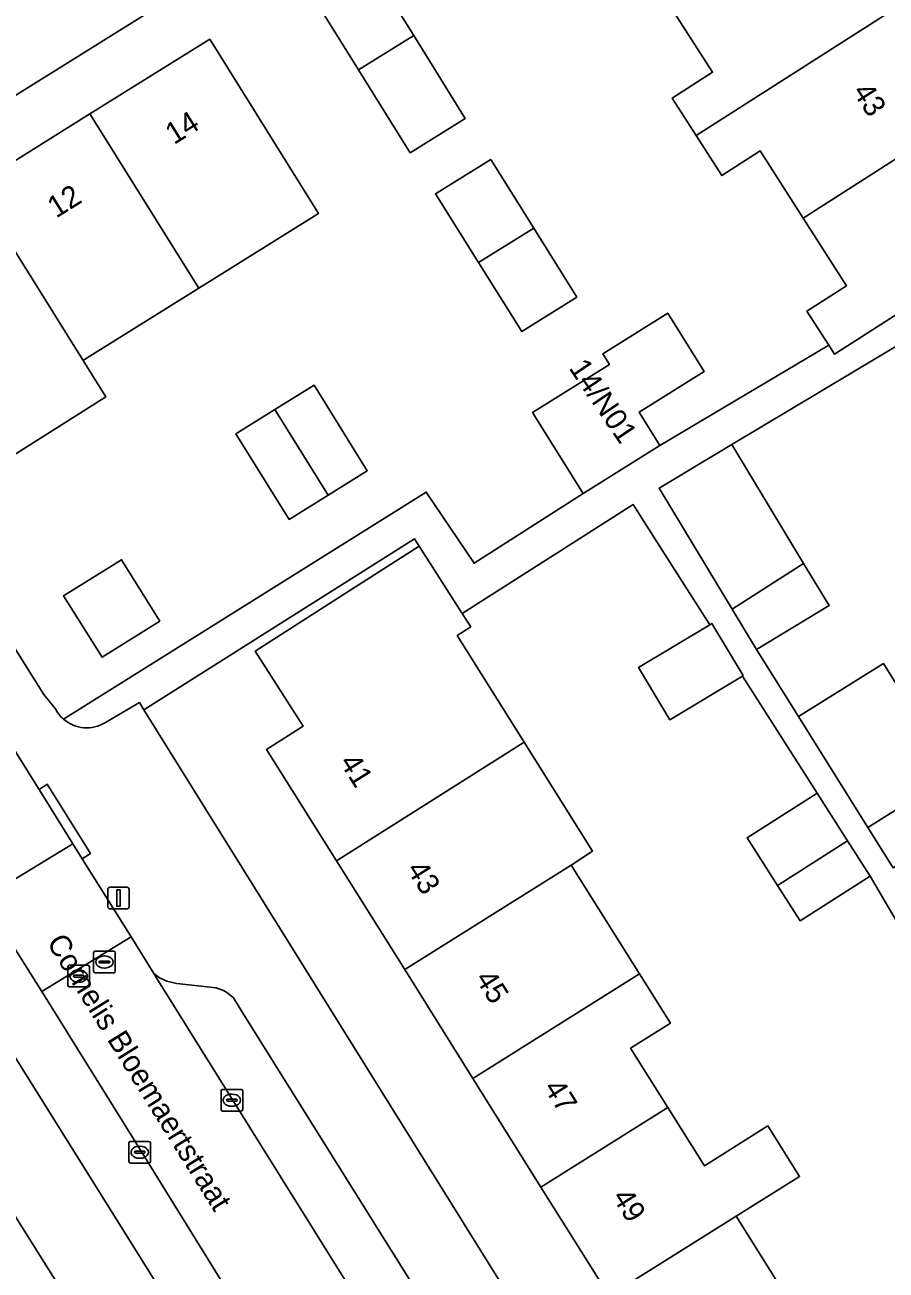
# Model space of a CAD drawing. Extents: x 159664 to 160323, y 385312 to 386115.
# Drawn here: x 160068.3 to 160108.1, y 385782.7 to 385840.2 of the extents above; entities that cross this region are included whole.
import ezdxf

# ---------------------------------------------------------------- set-up
doc = ezdxf.new("R2010")
doc.units = 0
for name, color, linetype in [('IMGEO_Erf', 7, 'Continuous'), ('IMGEO_Kolk', 7, 'Continuous'), ('IMGEO_Lichtmast', 7, 'Continuous'), ('IMGEO_Openbare_ruimte_label', 7, 'Continuous'), ('IMGEO_Pand', 7, 'Continuous'), ('IMGEO_Pand_nummerreeks', 7, 'Continuous'), ('IMGEO_Parkeervlak_open', 7, 'Continuous'), ('IMGEO_Rijbaan_lokaal_open', 7, 'Continuous'), ('IMGEO_Rioolput', 7, 'Continuous'), ('IMGEO_Voetpad_open', 7, 'Continuous')]:
    doc.layers.add(name, color=color, linetype=linetype)

msp = doc.modelspace()

# ---------------------------------------------------------------- linework, layer by layer
at = {"layer": 'IMGEO_Erf'}
for points in [[(160099.993, 385857.035), (160056.287, 385829.749), (160069.138, 385809.263), (160069.666, 385808.627)], [(160086.806, 385818.618), (160089.016, 385815.333), (160094.051, 385818.558), (160091.722, 385822.304), (160095.272, 385824.511), (160094.96, 385825.013), (160097.966, 385826.883), (160099.644, 385824.185), (160096.637, 385822.315), (160097.601, 385820.765), (160105.402, 385825.407), (160104.395, 385826.978), (160106.228, 385828.152), (160104.224, 385831.28), (160102.237, 385834.382), (160100.465, 385833.247), (160099.285, 385835.089), (160098.172, 385836.826), (160100.037, 385838.02), (160097.783, 385841.539)], [(160109.115, 385825.717), (160100.925, 385820.823), (160104.238, 385815.326), (160105.416, 385813.372), (160102.062, 385811.351), (160104.012, 385808.255), (160107.927, 385810.699), (160111.128, 385805.573)], [(160070.045, 385808.133), (160086.806, 385818.618)], [(160111.176, 385794.277), (160107.313, 385800.874), (160104.076, 385798.81), (160103.033, 385800.445), (160101.627, 385802.649), (160104.864, 385804.713), (160101.416, 385810.12), (160098.061, 385808.099), (160096.609, 385810.51), (160099.902, 385812.494), (160097.599, 385816.106), (160096.366, 385818.04), (160088.474, 385813.007), (160088.865, 385812.396), (160088.236, 385811.993), (160091.332, 385807.058), (160094.486, 385802.031), (160093.507, 385801.382), (160096.658, 385796.361), (160098.084, 385794.087), (160096.249, 385792.925), (160097.968, 385790.185), (160099.656, 385787.495), (160102.592, 385789.336), (160104.054, 385787.003), (160101.119, 385785.163), (160104.27, 385780.142)], [(160095.257, 385781.488), (160092.108, 385786.51), (160088.959, 385791.532), (160085.81, 385796.554), (160082.66, 385801.577), (160079.432, 385806.725), (160081.117, 385807.804), (160078.901, 385811.265), (160083.112, 385813.961), (160086.481, 385816.118), (160086.259, 385816.465), (160073.759, 385808.564), (160107.875, 385753.788)], [(160094.38, 385750), (160062.581, 385800.858), (160046.077, 385790.539), (160045.381, 385790.102), (160047.281, 385787.076), (160041.478, 385783.432), (160042.208, 385782.014), (160044.187, 385783.22), (160046.139, 385780.014)], [(160058.795, 385780.788), (160055.579, 385785.924), (160056.192, 385786.308), (160052.934, 385791.512), (160054.578, 385792.541), (160056.533, 385793.765), (160060.771, 385796.418), (160064.029, 385791.215), (160067.245, 385786.079), (160070.46, 385780.943)]]:
    msp.add_lwpolyline(points, dxfattribs=at)
for points in [[(160081.3, 385841.944), (160083.846, 385843.53), (160086.227, 385839.709), (160088.607, 385835.888), (160086.061, 385834.302), (160083.68, 385838.123)], [(160072.002, 385823.018), (160066.486, 385819.543), (160060.393, 385829.308), (160065.925, 385832.759), (160071.271, 385836.094), (160076.804, 385839.545), (160081.828, 385831.49), (160076.298, 385828.035), (160071.149, 385824.817), (160070.955, 385824.696)], [(160087.24, 385832.404), (160089.784, 385833.993), (160091.772, 385830.811), (160093.76, 385827.629), (160091.216, 385826.039), (160089.228, 385829.222)], [(160080.476, 385817.354), (160078.012, 385821.308), (160079.817, 385822.432), (160081.622, 385823.557), (160084.085, 385819.603), (160082.281, 385818.479)], [(160074.495, 385812.656), (160071.837, 385810.986), (160070.053, 385813.831), (160072.729, 385815.492)]]:
    msp.add_lwpolyline(points, close=True, dxfattribs=at)
msp.add_arc((160071.108, 385809.341), 1.61, 206.34306, 228.64825, dxfattribs=at)
at = {"layer": 'IMGEO_Kolk'}
for p, q in [((160077.325, 385790.097), (160077.325, 385790.949)), ((160077.4, 385791.023), (160078.252, 385791.023)), ((160078.326, 385790.949), (160078.326, 385790.097)), ((160077.584, 385790.517), (160077.584, 385790.529)), ((160078.022, 385790.48), (160077.624, 385790.48)), ((160077.627, 385790.566), (160078.025, 385790.566)), ((160077.813, 385790.803), (160077.838, 385790.803)), ((160078.068, 385790.529), (160078.068, 385790.517)), ((160078.252, 385790.023), (160077.4, 385790.023)), ((160077.836, 385790.243), (160077.811, 385790.243)), ((160073.144, 385788.62), (160073.996, 385788.62)), ((160073.069, 385787.694), (160073.069, 385788.546)), ((160073.328, 385788.114), (160073.328, 385788.126)), ((160073.766, 385788.077), (160073.368, 385788.077)), ((160073.371, 385788.163), (160073.769, 385788.163)), ((160073.557, 385788.4), (160073.582, 385788.4)), ((160073.812, 385788.126), (160073.812, 385788.114)), ((160074.07, 385788.546), (160074.07, 385787.694)), ((160073.996, 385787.62), (160073.144, 385787.62)), ((160073.58, 385787.84), (160073.555, 385787.84))]:
    msp.add_line(p, q, dxfattribs=at)
for points in [[(160077.325, 385790.097), (160077.325, 385790.949)], [(160077.4, 385791.023), (160078.252, 385791.023)], [(160078.326, 385790.949), (160078.326, 385790.097)], [(160078.252, 385790.023), (160077.4, 385790.023)], [(160073.144, 385788.62), (160073.996, 385788.62)], [(160073.069, 385787.694), (160073.069, 385788.546)], [(160074.07, 385788.546), (160074.07, 385787.694)], [(160073.996, 385787.62), (160073.144, 385787.62)]]:
    msp.add_lwpolyline(points, dxfattribs=at)
for centre, radius, start, end in [((160077.402, 385790.947), 0.0765, 91.55205, 178.44795), ((160077.402, 385790.947), 0.0765, 91.55205, 178.44795), ((160078.25, 385790.947), 0.0765, 1.55205, 88.44795), ((160078.25, 385790.947), 0.0765, 1.55205, 88.44795), ((160077.624, 385790.526), 0.0403, 85.87752, 175.75265), ((160077.621, 385790.516), 0.0366, 178.93798, 274.71019), ((160078.025, 385790.523), 0.043, 264.86636, 352.45326), ((160078.029, 385790.528), 0.0386, 1.73085, 96.63898), ((160077.402, 385790.099), 0.0765, 181.55205, 268.44795), ((160077.402, 385790.099), 0.0765, 181.55205, 268.44795), ((160078.25, 385790.099), 0.0765, 271.55205, 358.44795), ((160078.25, 385790.099), 0.0765, 271.55205, 358.44795), ((160073.146, 385788.544), 0.0765, 91.55205, 178.44795), ((160073.146, 385788.544), 0.0765, 91.55205, 178.44795), ((160073.994, 385788.544), 0.0765, 1.55205, 88.44795), ((160073.994, 385788.544), 0.0765, 1.55205, 88.44795), ((160073.368, 385788.123), 0.0403, 85.87752, 175.75265), ((160073.365, 385788.113), 0.0366, 178.93798, 274.71019), ((160073.769, 385788.12), 0.043, 264.86636, 352.45326), ((160073.773, 385788.125), 0.0386, 1.73085, 96.63898), ((160073.146, 385787.696), 0.0765, 181.55205, 268.44795), ((160073.146, 385787.696), 0.0765, 181.55205, 268.44795), ((160073.994, 385787.696), 0.0765, 271.55205, 358.44795), ((160073.994, 385787.696), 0.0765, 271.55205, 358.44795)]:
    msp.add_arc(centre, radius, start, end, dxfattribs=at)
for centre, major_axis, ratio, start_param, end_param in [((160077.812, 385790.523), (-0.387, 0.002), 0.722429, 4.712389, 7.853982), ((160077.837, 385790.523), (-0.39, 0.002), 0.717154, 1.570796, 4.712389), ((160073.556, 385788.12), (-0.387, 0.002), 0.722429, 4.712389, 7.853982), ((160073.581, 385788.12), (-0.39, 0.002), 0.717154, 1.570796, 4.712389)]:
    msp.add_ellipse(centre, major_axis=major_axis, ratio=ratio, start_param=start_param, end_param=end_param, dxfattribs=at)
at = {"layer": 'IMGEO_Lichtmast'}
for p, q in [((160072.09, 385799.461), (160072.09, 385800.261)), ((160072.09, 385800.261), (160072.09, 385799.461)), ((160072.19, 385800.361), (160072.98, 385800.361)), ((160072.98, 385800.361), (160072.19, 385800.361)), ((160073.08, 385800.261), (160073.08, 385799.461)), ((160073.08, 385799.461), (160073.08, 385800.261)), ((160072.98, 385799.361), (160072.19, 385799.361)), ((160072.19, 385799.361), (160072.98, 385799.361))]:
    msp.add_line(p, q, dxfattribs=at)
msp.add_lwpolyline([(160072.51, 385800.236), (160072.66, 385800.236), (160072.66, 385799.486), (160072.51, 385799.486), (160072.51, 385800.236)], dxfattribs=at)
for centre, start, end in [((160072.19, 385800.261), 90, 180), ((160072.19, 385800.261), 90, 180), ((160072.98, 385800.261), 0, 90), ((160072.98, 385800.261), 360, 90), ((160072.19, 385799.461), 180, 270), ((160072.19, 385799.461), 180, 270), ((160072.98, 385799.461), 270, 0), ((160072.98, 385799.461), 270, 0)]:
    msp.add_arc(centre, 0.1, start, end, dxfattribs=at)
at = {"layer": 'IMGEO_Pand'}
for points in [[(160109.361, 385841.542), (160107.77, 385844.025), (160106.493, 385843.207), (160104.71, 385845.99), (160097.783, 385841.539), (160100.037, 385838.02), (160098.172, 385836.826), (160099.285, 385835.089)], [(160086.227, 385839.709), (160083.846, 385843.53), (160081.3, 385841.944), (160083.68, 385838.123)], [(160099.285, 385835.089), (160100.465, 385833.247), (160102.237, 385834.382), (160104.224, 385831.28), (160111.232, 385835.764), (160109.653, 385838.228), (160110.951, 385839.059), (160109.361, 385841.542)], [(160076.298, 385828.035), (160081.828, 385831.49), (160076.804, 385839.545), (160071.271, 385836.094)], [(160083.68, 385838.123), (160086.061, 385834.302), (160088.607, 385835.888), (160086.227, 385839.709)], [(160071.271, 385836.094), (160065.925, 385832.759), (160070.955, 385824.696), (160071.149, 385824.817), (160076.298, 385828.035)], [(160115.741, 385831.449), (160114.046, 385834.094), (160112.809, 385833.302), (160111.232, 385835.764), (160104.224, 385831.28), (160106.228, 385828.152), (160104.395, 385826.978), (160105.402, 385825.407), (160105.666, 385824.995), (160111.531, 385828.752)], [(160091.772, 385830.811), (160089.784, 385833.993), (160087.24, 385832.404), (160089.228, 385829.222)], [(160065.925, 385832.759), (160060.393, 385829.308), (160066.486, 385819.543), (160072.002, 385823.018), (160070.955, 385824.696)], [(160089.228, 385829.222), (160091.216, 385826.039), (160093.76, 385827.629), (160091.772, 385830.811)], [(160095.272, 385824.511), (160091.722, 385822.304), (160094.051, 385818.558), (160097.601, 385820.765), (160096.637, 385822.315), (160099.644, 385824.185), (160097.966, 385826.883), (160094.96, 385825.013)], [(160082.281, 385818.479), (160084.085, 385819.603), (160081.622, 385823.557), (160079.817, 385822.432)], [(160079.817, 385822.432), (160078.012, 385821.308), (160080.476, 385817.354), (160082.281, 385818.479)], [(160100.925, 385820.823), (160097.572, 385818.803), (160100.94, 385813.213), (160104.238, 385815.326)], [(160088.236, 385811.993), (160088.865, 385812.396), (160088.474, 385813.007), (160086.481, 385816.118), (160083.112, 385813.961), (160078.901, 385811.265), (160081.117, 385807.804), (160079.432, 385806.725), (160082.66, 385801.577), (160091.332, 385807.058)], [(160074.495, 385812.656), (160072.729, 385815.492), (160070.053, 385813.831), (160071.837, 385810.986)], [(160104.238, 385815.326), (160100.94, 385813.213), (160102.062, 385811.351), (160105.416, 385813.372)], [(160099.902, 385812.494), (160096.609, 385810.51), (160098.061, 385808.099), (160101.416, 385810.12), (160101.448, 385810.139), (160099.996, 385812.55)], [(160104.012, 385808.255), (160107.213, 385803.129), (160110.681, 385805.294), (160111.128, 385805.573), (160107.927, 385810.699)], [(160094.486, 385802.031), (160091.332, 385807.058), (160082.66, 385801.577), (160085.81, 385796.554), (160093.507, 385801.382)], [(160110.681, 385805.294), (160107.213, 385803.129), (160108.377, 385801.265), (160111.845, 385803.431)], [(160106.27, 385802.508), (160104.864, 385804.713), (160101.627, 385802.649), (160103.033, 385800.445)], [(160103.033, 385800.445), (160104.076, 385798.81), (160107.313, 385800.874), (160106.27, 385802.508)], [(160085.81, 385796.554), (160088.959, 385791.532), (160096.658, 385796.361), (160093.507, 385801.382)], [(160097.968, 385790.185), (160096.249, 385792.925), (160098.084, 385794.087), (160096.658, 385796.361), (160088.959, 385791.532), (160092.108, 385786.51)], [(160097.968, 385790.185), (160092.108, 385786.51), (160095.257, 385781.488), (160101.119, 385785.163), (160104.054, 385787.003), (160102.592, 385789.336), (160099.656, 385787.495)], [(160070.46, 385780.943), (160067.245, 385786.079), (160058.795, 385780.788), (160055.645, 385778.816), (160058.861, 385773.679), (160062.011, 385775.652)], [(160095.257, 385781.488), (160098.407, 385776.465), (160104.27, 385780.142), (160101.119, 385785.163)]]:
    msp.add_lwpolyline(points, close=True, dxfattribs=at)
at = {"layer": 'IMGEO_Parkeervlak_open'}
msp.add_lwpolyline([(160104.908, 385752.055), (160078.293, 385794.618), (160077.902, 385795.251), (160077.641, 385795.461), (160077.434, 385795.585), (160077.095, 385795.707), (160075.283, 385795.911), (160074.828, 385796.027), (160074.486, 385796.179), (160074.219, 385796.37), (160074.364, 385796.138), (160103.162, 385750)], dxfattribs=at)
at = {"layer": 'IMGEO_Rijbaan_lokaal_open'}
for points in [[(160055.784, 385825.734), (160051.714, 385823.214), (160064.933, 385802.158), (160066.326, 385799.84), (160070.48, 385802.371), (160068.918, 385804.881), (160066.947, 385808.01), (160064.936, 385811.203)], [(160073.17, 385798.066), (160070.911, 385801.681), (160070.48, 385802.371), (160066.326, 385799.84), (160067.02, 385798.749), (160069.054, 385795.552)], [(160074.364, 385796.138), (160074.219, 385796.37), (160073.891, 385796.895), (160073.17, 385798.066), (160069.054, 385795.552), (160073.21, 385788.865), (160087.96, 385765.011), (160097.356, 385750), (160098.099, 385748.813), (160101.521, 385743.346), (160102.424, 385741.904), (160106.593, 385744.513), (160103.162, 385750)]]:
    msp.add_lwpolyline(points, close=True, dxfattribs=at)
at = {"layer": 'IMGEO_Rioolput'}
for p, q in [((160071.441, 385796.482), (160071.441, 385797.334)), ((160071.516, 385797.408), (160072.368, 385797.408)), ((160072.442, 385797.334), (160072.442, 385796.482)), ((160070.25, 385795.828), (160070.25, 385796.68)), ((160070.325, 385796.754), (160071.177, 385796.754)), ((160071.251, 385796.68), (160071.251, 385795.828)), ((160071.7, 385796.902), (160071.7, 385796.914)), ((160072.138, 385796.865), (160071.74, 385796.865)), ((160071.743, 385796.951), (160072.141, 385796.951)), ((160071.929, 385797.188), (160071.954, 385797.188)), ((160072.184, 385796.914), (160072.184, 385796.902)), ((160070.509, 385796.248), (160070.509, 385796.26)), ((160070.947, 385796.211), (160070.549, 385796.211)), ((160070.552, 385796.297), (160070.95, 385796.297)), ((160070.738, 385796.534), (160070.763, 385796.534)), ((160070.993, 385796.26), (160070.993, 385796.248)), ((160072.368, 385796.408), (160071.516, 385796.408)), ((160071.952, 385796.628), (160071.927, 385796.628)), ((160071.177, 385795.754), (160070.325, 385795.754)), ((160070.761, 385795.974), (160070.736, 385795.974))]:
    msp.add_line(p, q, dxfattribs=at)
for points in [[(160071.441, 385796.482), (160071.441, 385797.334)], [(160071.516, 385797.408), (160072.368, 385797.408)], [(160072.442, 385797.334), (160072.442, 385796.482)], [(160070.25, 385795.828), (160070.25, 385796.68)], [(160070.325, 385796.754), (160071.177, 385796.754)], [(160071.251, 385796.68), (160071.251, 385795.828)], [(160072.368, 385796.408), (160071.516, 385796.408)], [(160071.177, 385795.754), (160070.325, 385795.754)]]:
    msp.add_lwpolyline(points, dxfattribs=at)
for centre, radius, start, end in [((160071.518, 385797.332), 0.0765, 91.55205, 178.44795), ((160071.518, 385797.332), 0.0765, 91.55205, 178.44795), ((160072.366, 385797.332), 0.0765, 1.55205, 88.44795), ((160072.366, 385797.332), 0.0765, 1.55205, 88.44795), ((160070.327, 385796.678), 0.0765, 91.55205, 178.44795), ((160070.327, 385796.678), 0.0765, 91.55205, 178.44795), ((160071.175, 385796.678), 0.0765, 1.55205, 88.44795), ((160071.175, 385796.678), 0.0765, 1.55205, 88.44795), ((160071.74, 385796.911), 0.0403, 85.87752, 175.75265), ((160071.737, 385796.901), 0.0366, 178.93798, 274.71019), ((160072.141, 385796.908), 0.043, 264.86636, 352.45326), ((160072.145, 385796.913), 0.0386, 1.73085, 96.63898), ((160070.549, 385796.257), 0.0403, 85.87752, 175.75265), ((160070.546, 385796.247), 0.0366, 178.93798, 274.71019), ((160070.95, 385796.254), 0.043, 264.86636, 352.45326), ((160070.954, 385796.259), 0.0386, 1.73085, 96.63898), ((160071.518, 385796.484), 0.0765, 181.55205, 268.44795), ((160071.518, 385796.484), 0.0765, 181.55205, 268.44795), ((160072.366, 385796.484), 0.0765, 271.55205, 358.44795), ((160072.366, 385796.484), 0.0765, 271.55205, 358.44795), ((160070.327, 385795.83), 0.0765, 181.55205, 268.44795), ((160070.327, 385795.83), 0.0765, 181.55205, 268.44795), ((160071.175, 385795.83), 0.0765, 271.55205, 358.44795), ((160071.175, 385795.83), 0.0765, 271.55205, 358.44795)]:
    msp.add_arc(centre, radius, start, end, dxfattribs=at)
for centre, major_axis, ratio, start_param, end_param in [((160071.928, 385796.908), (-0.387, 0.002), 0.722429, 4.712389, 7.853982), ((160071.953, 385796.908), (-0.39, 0.002), 0.717154, 1.570796, 4.712389), ((160070.737, 385796.254), (-0.387, 0.002), 0.722429, 4.712389, 7.853982), ((160070.762, 385796.254), (-0.39, 0.002), 0.717154, 1.570796, 4.712389)]:
    msp.add_ellipse(centre, major_axis=major_axis, ratio=ratio, start_param=start_param, end_param=end_param, dxfattribs=at)
at = {"layer": 'IMGEO_Voetpad_open'}
for points in [[(160054.069, 385833.285), (160056.287, 385829.749), (160099.993, 385857.035)], [(160108.377, 385801.265), (160107.213, 385803.129), (160104.012, 385808.255), (160102.062, 385811.351), (160100.94, 385813.213), (160097.572, 385818.803), (160100.925, 385820.823), (160109.115, 385825.717), (160110.565, 385826.622), (160114.806, 385829.27), (160119.147, 385831.981), (160118.41, 385833.159), (160115.741, 385831.449), (160111.531, 385828.752), (160105.666, 385824.995), (160105.402, 385825.407), (160097.601, 385820.765), (160094.051, 385818.558), (160089.016, 385815.333), (160086.806, 385818.618), (160070.045, 385808.133)], [(160069.666, 385808.627), (160069.138, 385809.263), (160056.287, 385829.749)], [(160045.59, 385828.012), (160047.785, 385824.505), (160061.979, 385801.821), (160062.581, 385800.858), (160094.38, 385750), (160095.955, 385747.471), (160098.099, 385748.813), (160097.356, 385750), (160087.96, 385765.011), (160073.21, 385788.865), (160069.054, 385795.552), (160067.02, 385798.749), (160066.548, 385798.452), (160064.434, 385801.844), (160064.933, 385802.158), (160051.714, 385823.214)], [(160054.433, 385827.91), (160055.784, 385825.734), (160064.936, 385811.203), (160065.393, 385811.497), (160067.38, 385808.306), (160066.947, 385808.01), (160068.918, 385804.881), (160069.3, 385805.119), (160071.297, 385801.921), (160070.911, 385801.681), (160073.17, 385798.066), (160073.891, 385796.895), (160074.219, 385796.37), (160074.486, 385796.179), (160074.828, 385796.027), (160075.283, 385795.911), (160077.095, 385795.707), (160077.434, 385795.585), (160077.641, 385795.461), (160077.902, 385795.251), (160078.293, 385794.618), (160104.908, 385752.055)], [(160071.982, 385807.98), (160073.555, 385808.892), (160073.759, 385808.564), (160086.259, 385816.465), (160086.481, 385816.118), (160088.474, 385813.007), (160096.366, 385818.04), (160097.599, 385816.106), (160099.902, 385812.494), (160099.996, 385812.55), (160101.448, 385810.139), (160101.416, 385810.12), (160104.864, 385804.713), (160106.27, 385802.508), (160107.313, 385800.874), (160111.176, 385794.277), (160112.376, 385792.302), (160113.524, 385790.411), (160117.498, 385784.113), (160118.696, 385782.233)], [(160107.875, 385753.788), (160073.759, 385808.564), (160073.555, 385808.892), (160071.982, 385807.98)]]:
    msp.add_lwpolyline(points, dxfattribs=at)
msp.add_lwpolyline([(160070.48, 385802.371), (160070.911, 385801.681), (160071.297, 385801.921), (160069.3, 385805.119), (160068.918, 385804.881)], close=True, dxfattribs=at)
for centre, radius, start, end in [((160071.108, 385809.341), 1.61, 206.34306, 228.64825), ((160071.115, 385809.346), 1.618, 228.57946, 302.38793), ((160071.115, 385809.346), 1.618, 228.57946, 302.38793)]:
    msp.add_arc(centre, radius, start, end, dxfattribs=at)

# ---------------------------------------------------------------- texts
at = {"layer": 'IMGEO_Openbare_ruimte_label'}
msp.add_text('Cornelis Bloemaertstraat', height=1, rotation=301.92646, dxfattribs=at).set_placement((160069.246, 385797.813))
at = {"layer": 'IMGEO_Pand_nummerreeks'}
for s, rotation, p in [('43', 302.58508, (160106.474, 385837.131)), ('14', 31.95551, (160075.152, 385834.649)), ('12', 31.95386, (160069.708, 385831.253)), ('14/N01', 304.1137, (160093.368, 385824.35)), ('41', 302.09116, (160082.772, 385806.144)), ('43', 302.0906, (160085.876, 385801.192)), ('45', 302.0906, (160089.041, 385796.145)), ('47', 302.0906, (160092.206, 385791.097)), ('49', 302.0906, (160095.371, 385786.049))]:
    msp.add_text(s, height=1, rotation=rotation, dxfattribs=at).set_placement(p)

doc.saveas('drawing.dxf')
